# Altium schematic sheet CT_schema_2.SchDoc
size 521 x 498 mm
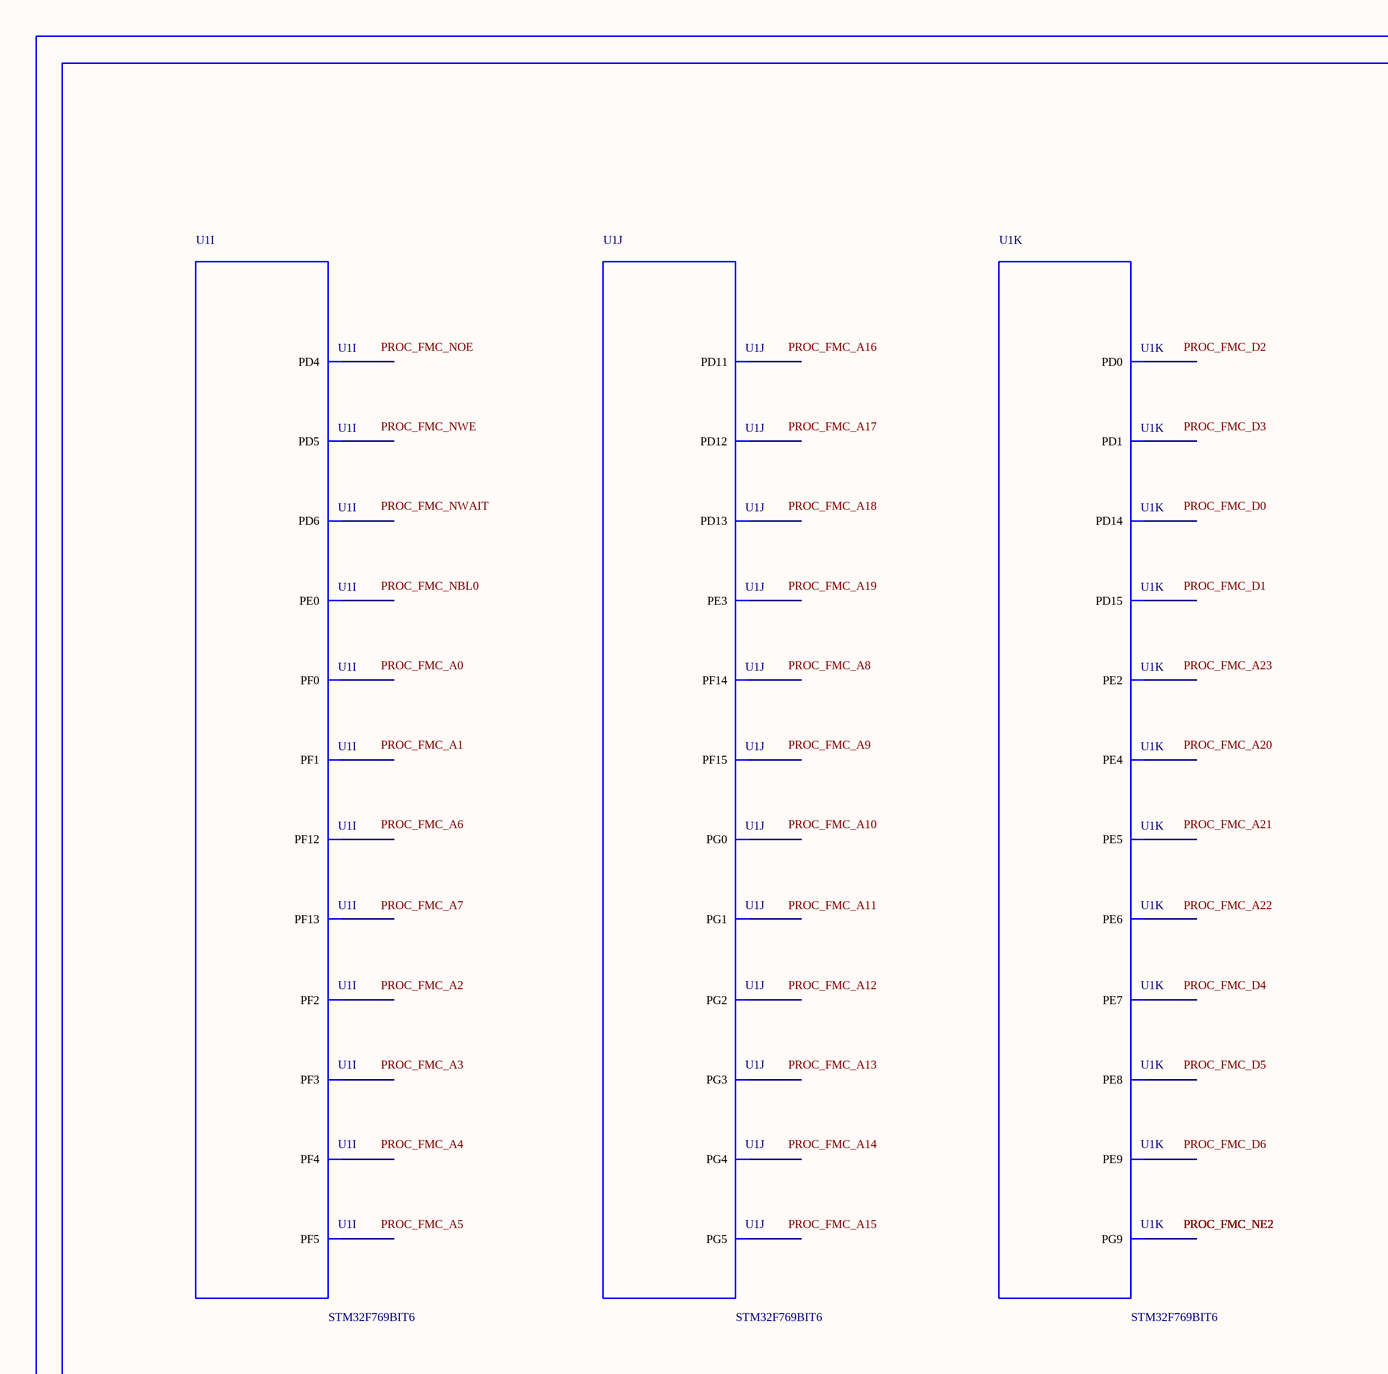
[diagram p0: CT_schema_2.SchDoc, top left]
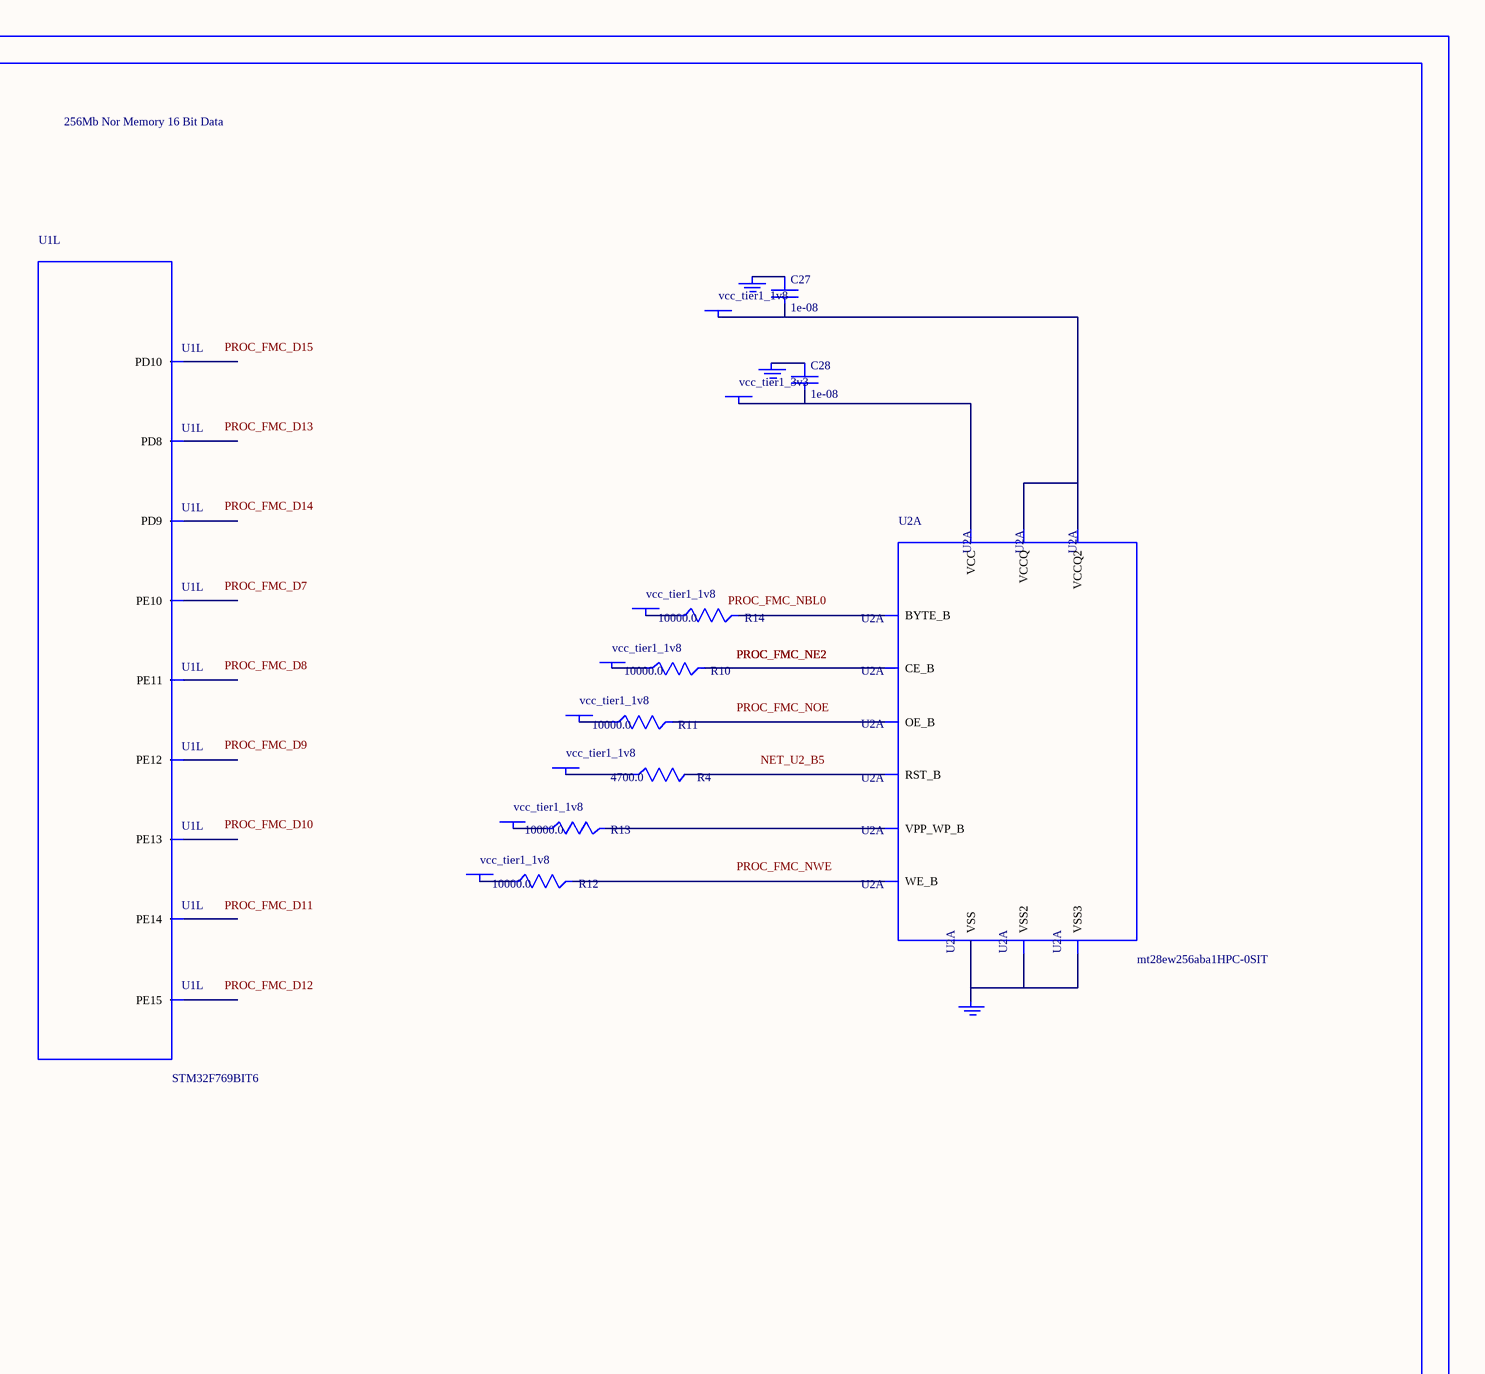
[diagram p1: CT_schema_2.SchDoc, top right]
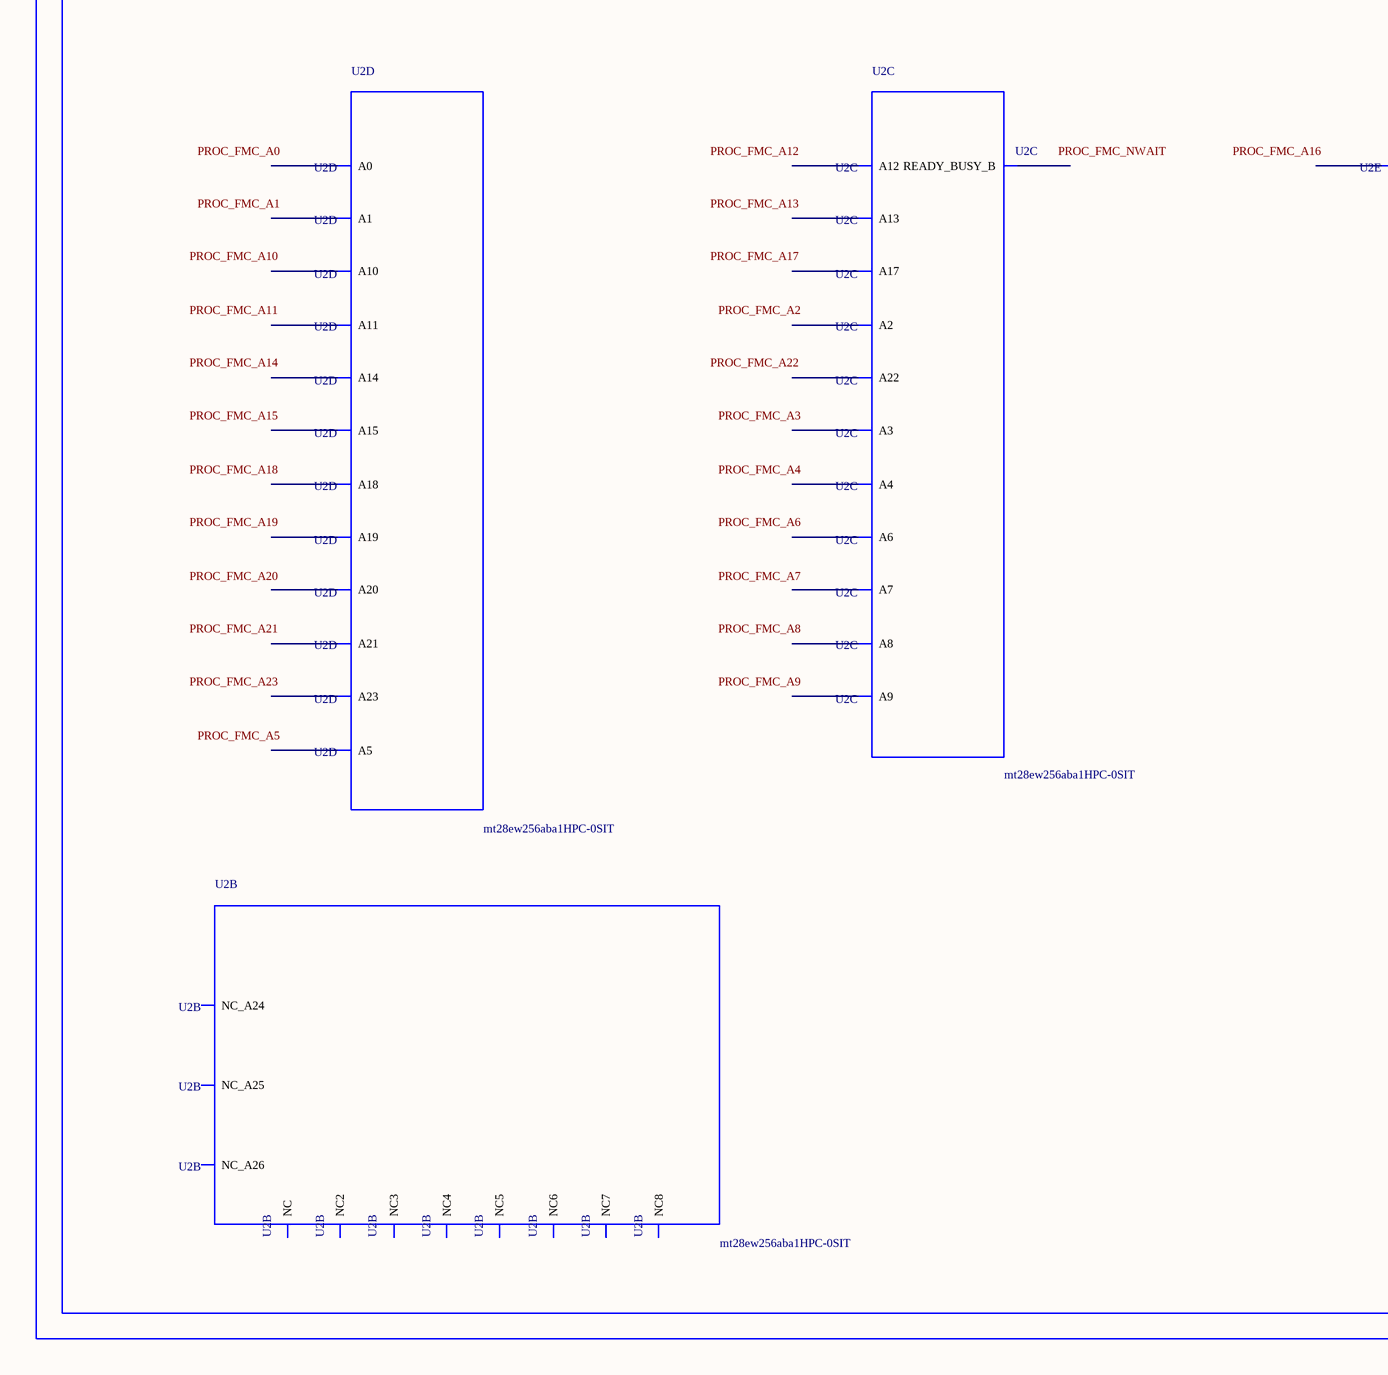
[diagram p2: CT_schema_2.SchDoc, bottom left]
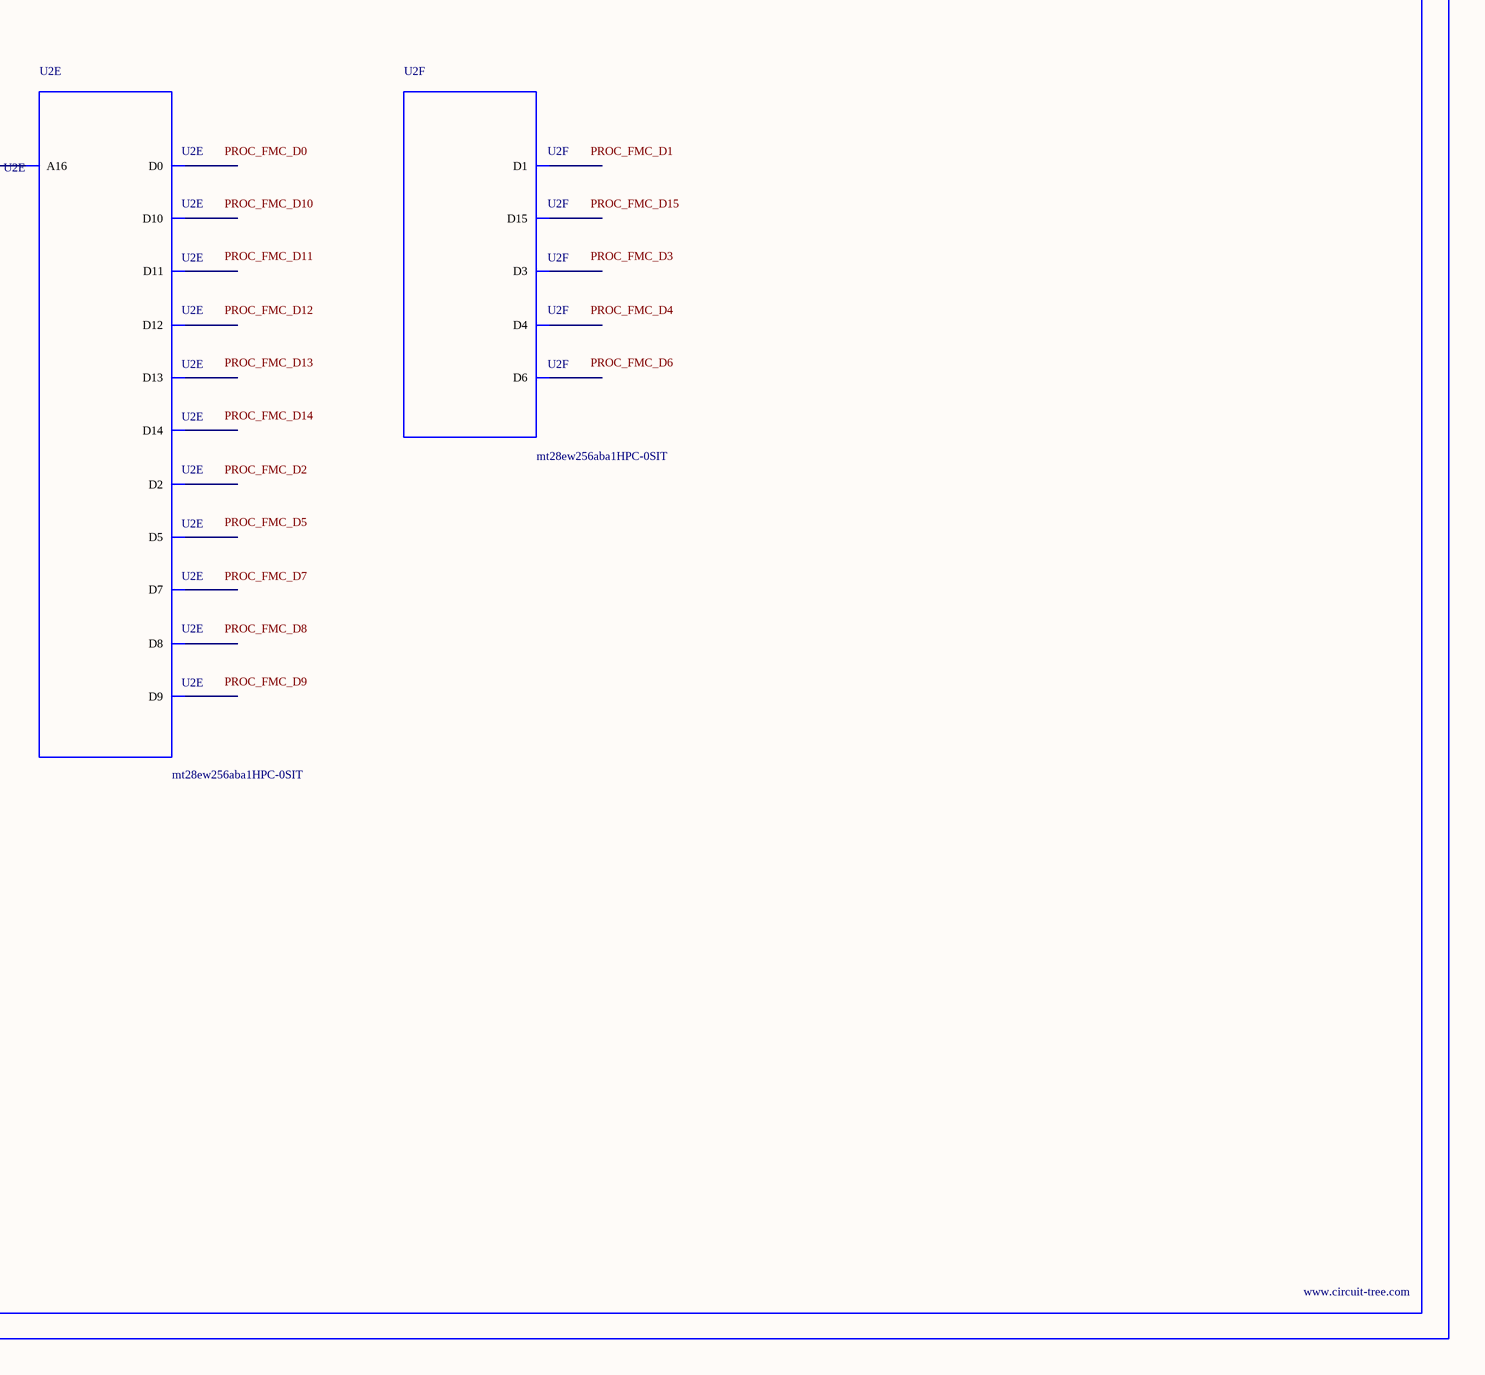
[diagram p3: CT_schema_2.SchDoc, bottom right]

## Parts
BORDER1  (no value)
C27  1e-08  [C0402]
C28  1e-08  [C0402]
GND_INSTANCE_1_0  (no value)
GND_INSTANCE_1_1  (no value)
GND_INSTANCE_1_2  (no value)
POWER_INSTANCE_1_0  vcc_tier1_1v8
POWER_INSTANCE_1_1  vcc_tier1_3v3
POWER_INSTANCE_1_2  vcc_tier1_1v8
POWER_INSTANCE_1_3  vcc_tier1_1v8
POWER_INSTANCE_1_4  vcc_tier1_1v8
POWER_INSTANCE_1_5  vcc_tier1_1v8
POWER_INSTANCE_1_6  vcc_tier1_1v8
POWER_INSTANCE_1_7  vcc_tier1_1v8
R4  4700.0  [R0603]
R10  10000.0  [R0603]
R11  10000.0  [R0603]
R12  10000.0  [R0603]
R13  10000.0  [R0603]
R14  10000.0  [R0603]
U1  STM32F769BIT6  [LQFP208]  (parts I,J,K,L of 15)
U2  mt28ew256aba1HPC-0SIT  [LBGA-64]  (parts A,B,C,D,E,F of 6)

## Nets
NetC27_1: C27.1 GND_INSTANCE_1_0.0(GND)
NetC27_2: C27.2 POWER_INSTANCE_1_0.0(PWR) U2.D8(VCCQ) U2.F1(VCCQ2)
NetC28_1: C28.1 GND_INSTANCE_1_1.0(GND)
NetC28_2: C28.2 POWER_INSTANCE_1_1.0(PWR) U2.G5(VCC)
NetGND_INSTANCE_1_2_0: GND_INSTANCE_1_2.0(GND) U2.E8(VSS) U2.H2(VSS2) U2.H7(VSS3)
NetPOWER_INSTANCE_1_2_0: POWER_INSTANCE_1_2.0(PWR) R10.1
NetPOWER_INSTANCE_1_3_0: POWER_INSTANCE_1_3.0(PWR) R11.1
NetPOWER_INSTANCE_1_4_0: POWER_INSTANCE_1_4.0(PWR) R12.1
NetPOWER_INSTANCE_1_5_0: POWER_INSTANCE_1_5.0(PWR) R13.1
NetPOWER_INSTANCE_1_6_0: POWER_INSTANCE_1_6.0(PWR) R14.1
NetPOWER_INSTANCE_1_7_0: POWER_INSTANCE_1_7.0(PWR) R4.1
NetR4_2: R4.2 U2.B5(RST_B)
NetR10_2: R10.2 U2.F2(CE_B)
NetR11_2: R11.2 U2.G2(OE_B)
NetR12_2: R12.2 U2.A5(WE_B)
NetR13_2: R13.2 U2.B4(VPP_WP_B)
NetR14_2: R14.2 U2.F7(BYTE_B)

Not connected (* = marked no-connect by the designer): U1 1(PE2) 2(PE3) 3(PE4) 4(PE5) 5(PE6) 16(PF0) 17(PF1) 18(PF2) 22(PF3) 23(PF4) 24(PF5) 71(PF12) 74(PF13) 75(PF14) 76(PF15) 77(PG0) 78(PG1) 79(PE7) 80(PE8) 81(PE9) 84(PE10) 85(PE11) 86(PE12) 87(PE13) 88(PE14) 89(PE15) 108(PD8) 109(PD9) 110(PD10) 111(PD11) 112(PD12) 113(PD13) 116(PD14) 117(PD15) 129(PG2) 130(PG3) 131(PG4) 132(PG5) 164(PD0) 165(PD1) 168(PD4) 169(PD5) 172(PD6) 178(PG9) 200(PE0); U2 A1(NC) A2(A3) A3(A7) A4(READY_BUSY_B) A6(A9) A7(A13) A8(NC2) B1(NC_A26) B2(A4) B3(A17) B6(A8) B7(A12) B8(A22) C1(NC3) C2(A2) C3(A6) C4(A18) C5(A21) C6(A10) C7(A14) C8(A23) D1(NC4) D2(A1) D3(A5) D4(A20) D5(A19) D6(A11) D7(A15) E1(NC5) E2(A0) E3(D0) E4(D2) E5(D5) E6(D7) E7(A16) F3(D8) F4(D10) F5(D12) F6(D14) F8(NC_A24) G1(NC6) G3(D9) G4(D11) G6(D13) G7(D15) G8(NC_A25) H1(NC7) H3(D1) H4(D3) H5(D4) H6(D6) H8(NC8)

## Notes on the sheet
- Labels drawn without touching a wire or pin: NET_U2_B5, PROC_FMC_A0, PROC_FMC_A1, PROC_FMC_A2, PROC_FMC_A3, PROC_FMC_A4, PROC_FMC_A5, PROC_FMC_A6, PROC_FMC_A7, PROC_FMC_A8, PROC_FMC_A9, PROC_FMC_A10, PROC_FMC_A11, PROC_FMC_A12, PROC_FMC_A13, PROC_FMC_A14, PROC_FMC_A15, PROC_FMC_A16, PROC_FMC_A17, PROC_FMC_A18, PROC_FMC_A19, PROC_FMC_A20, PROC_FMC_A21, PROC_FMC_A22, PROC_FMC_A23, PROC_FMC_D0, PROC_FMC_D1, PROC_FMC_D2, PROC_FMC_D3, PROC_FMC_D4, PROC_FMC_D5, PROC_FMC_D6, PROC_FMC_D7, PROC_FMC_D8, PROC_FMC_D9, PROC_FMC_D10, PROC_FMC_D11, PROC_FMC_D12, PROC_FMC_D13, PROC_FMC_D14, PROC_FMC_D15, PROC_FMC_NBL0, PROC_FMC_NOE, PROC_FMC_NWAIT, PROC_FMC_NWE

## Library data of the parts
BORDER1 = BORDER_PAGE1
C27 C28 = C0402C103K3RAC
GND_INSTANCE_1_0-GND_INSTANCE_1_2 = GND
POWER_INSTANCE_1_0-POWER_INSTANCE_1_7 = PWR
R4 = RC0603JR-074K7L
R10-R14 = RC0603JR-0710KL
